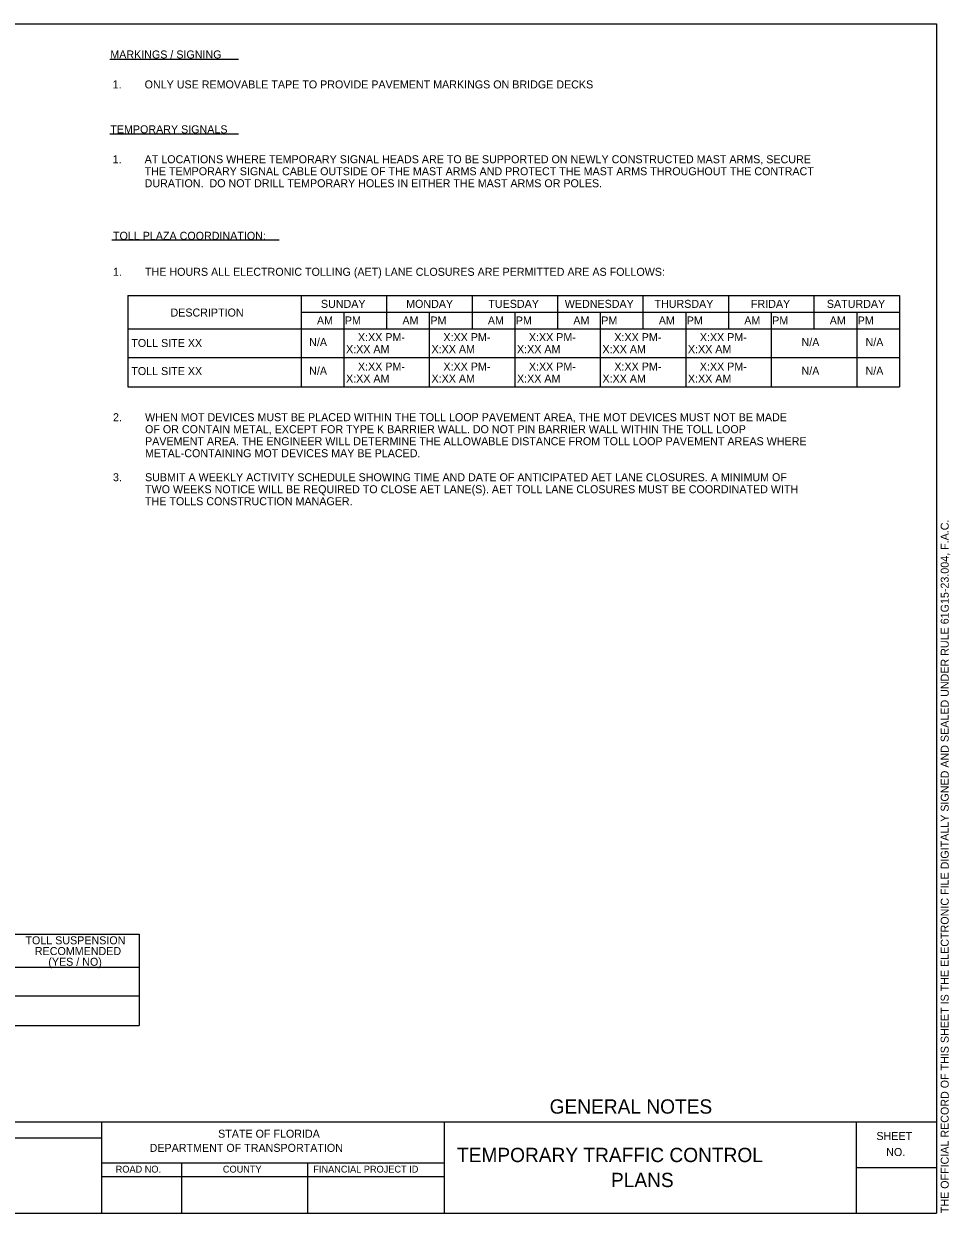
# Model space of a CAD drawing. Extents: x -0.71 to 1.34, y 0 to 0.87.
# Drawn here: x 0.664 to 1.339, y 0.004 to 0.871 of the extents above; entities that cross this region are included whole.
import ezdxf

# ---------------------------------------------------------------- set-up
doc = ezdxf.new("R2010")
doc.units = 0
for name, color, linetype in [('Default', 7, 'Continuous'), ('SheetBorder_dp', 7, 'Continuous'), ('SheetLines_dp', 7, 'Continuous'), ('TextLabel', 7, 'Continuous'), ('TextMisc', 7, 'Continuous')]:
    doc.layers.add(name, color=color, linetype=linetype)

msp = doc.modelspace()

# ---------------------------------------------------------------- linework, layer by layer
at = {"layer": 'Default'}
for p, q in [((0.74007, 0.67283), (1.30218, 0.67283)), ((0.74007, 0.67283), (0.74007, 0.60627)), ((0.86628, 0.67283), (0.86628, 0.60627)), ((0.92855, 0.67283), (0.92855, 0.64857)), ((0.99082, 0.67283), (0.99082, 0.64857)), ((1.05309, 0.67283), (1.05309, 0.64857)), ((1.11536, 0.67283), (1.11536, 0.64857)), ((1.17763, 0.67283), (1.17763, 0.64857)), ((1.2399, 0.67283), (1.2399, 0.64857)), ((1.30218, 0.67283), (1.30218, 0.60627)), ((0.86628, 0.6607), (1.30218, 0.6607)), ((0.89741, 0.6607), (0.89741, 0.60627)), ((0.95968, 0.6607), (0.95968, 0.60627)), ((1.02196, 0.6607), (1.02196, 0.60627)), ((1.08423, 0.6607), (1.08423, 0.60627)), ((1.1465, 0.6607), (1.1465, 0.60627)), ((1.20877, 0.6607), (1.20877, 0.60627)), ((1.27104, 0.6607), (1.27104, 0.60627)), ((0.74007, 0.64857), (1.30218, 0.64857)), ((0.74007, 0.62768), (1.30218, 0.62768)), ((0.74007, 0.60627), (1.30218, 0.60627)), ((0.08359, 0.20761), (0.74834, 0.20761)), ((0.74834, 0.20761), (0.74834, 0.14105)), ((0.08359, 0.18334), (0.74834, 0.18334)), ((0.08359, 0.16246), (0.74834, 0.16246)), ((0.08359, 0.14105), (0.74834, 0.14105))]:
    msp.add_line(p, q, dxfattribs=at)
at = {"layer": 'SheetBorder_dp'}
for p, q in [((0.04583, 0.87083), (1.32916, 0.87083)), ((1.32916, 0.87083), (1.32916, 0.00417)), ((0.04583, 0.07083), (1.32916, 0.07083)), ((0.04583, 0.00417), (1.32916, 0.00417))]:
    msp.add_line(p, q, dxfattribs=at)
at = {"layer": 'SheetLines_dp'}
for p, q in [((0.72083, 0.07083), (0.72083, 0.00417)), ((0.97083, 0.00417), (0.97083, 0.07083)), ((1.27083, 0.00417), (1.27083, 0.07083)), ((0.52621, 0.05917), (0.72084, 0.05917)), ((0.72083, 0.04083), (0.97083, 0.04083)), ((0.77916, 0.04083), (0.77916, 0.00417)), ((0.87083, 0.04083), (0.87083, 0.00417)), ((1.27083, 0.0375), (1.32916, 0.0375)), ((0.72083, 0.03083), (0.97083, 0.03083))]:
    msp.add_line(p, q, dxfattribs=at)
at = {"layer": 'TextLabel'}
for p, q in [((0.72696, 0.84513), (0.8207, 0.84513)), ((0.72696, 0.79059), (0.8207, 0.79059)), ((0.7283, 0.71335), (0.85036, 0.71335))]:
    msp.add_line(p, q, dxfattribs=at)

# ---------------------------------------------------------------- texts
at = {"layer": 'Default'}
for s, height, p in [('SUNDAY', 0.005833, (0.88069, 0.66385)), ('MONDAY', 0.005833, (0.94278, 0.66385)), ('TUESDAY', 0.005833, (1.0027, 0.66385)), ('WEDNESDAY', 0.005833, (1.05836, 0.66385)), ('THURSDAY', 0.005833, (1.12372, 0.66385)), ('FRIDAY', 0.005833, (1.19401, 0.66385)), ('SATURDAY', 0.005833, (1.24932, 0.66385)), ('DESCRIPTION', 0.0058333, (0.77108, 0.65751)), ('AM    PM', 0.005833, (0.87779, 0.65172)), ('AM    PM', 0.005833, (0.94006, 0.65172)), ('AM    PM', 0.005833, (1.00233, 0.65172)), ('AM    PM', 0.005833, (1.0646, 0.65172)), ('AM    PM', 0.005833, (1.12687, 0.65172)), ('AM    PM', 0.005833, (1.18914, 0.65172)), ('AM    PM', 0.005833, (1.25141, 0.65172)), ('N/A', 0.005833, (0.87214, 0.63594)), (' X:XX PM-', 0.005833, (0.9055, 0.63958)), (' X:XX PM-', 0.005833, (0.96777, 0.63958)), (' X:XX PM-', 0.005833, (1.03005, 0.63958)), (' X:XX PM-', 0.005833, (1.09232, 0.63958)), (' X:XX PM-', 0.005833, (1.15459, 0.63958)), ('N/A', 0.005833, (1.23085, 0.63594)), ('N/A', 0.005833, (1.27751, 0.63594)), ('TOLL SITE XX', 0.0058333, (0.74255, 0.63532)), ('      X:XX AM', 0.0058333, (0.886, 0.63083)), ('      X:XX AM', 0.0058333, (0.94828, 0.63083)), ('      X:XX AM', 0.0058333, (1.01055, 0.63083)), ('      X:XX AM', 0.0058333, (1.07282, 0.63083)), ('      X:XX AM', 0.0058333, (1.13509, 0.63083)), (' X:XX PM-', 0.005833, (0.9055, 0.61817)), (' X:XX PM-', 0.005833, (0.96777, 0.61817)), (' X:XX PM-', 0.005833, (1.03005, 0.61817)), (' X:XX PM-', 0.005833, (1.09232, 0.61817)), (' X:XX PM-', 0.005833, (1.15459, 0.61817)), ('TOLL SITE XX', 0.0058333, (0.74255, 0.61487)), ('N/A', 0.005833, (0.87214, 0.61506)), ('N/A', 0.005833, (1.23085, 0.61506)), ('N/A', 0.005833, (1.27751, 0.61506)), ('      X:XX AM', 0.0058333, (0.886, 0.60942)), ('      X:XX AM', 0.0058333, (0.94828, 0.60942)), ('      X:XX AM', 0.0058333, (1.01055, 0.60942)), ('      X:XX AM', 0.0058333, (1.07282, 0.60942)), ('      X:XX AM', 0.0058333, (1.13509, 0.60942)), ('TOLL SUSPENSION ', 0.0058333, (0.66541, 0.20009)), ('RECOMMENDED', 0.0058333, (0.67228, 0.19227)), ('(YES / NO)', 0.005833, (0.68208, 0.18446))]:
    msp.add_text(s, height=height, dxfattribs=at).set_placement(p)
at = {"layer": 'TextLabel'}
for s, height, p in [('MARKINGS / SIGNING', 0.0058333, (0.72723, 0.84555)), ('1. ', 0.005833, (0.72892, 0.82374)), ('ONLY USE REMOVABLE TAPE TO PROVIDE PAVEMENT MARKINGS ON BRIDGE DECKS', 0.0058333, (0.75225, 0.82374)), ('TEMPORARY SIGNALS', 0.0058333, (0.72723, 0.79102)), ('1. ', 0.005833, (0.72892, 0.76921)), ('AT LOCATIONS WHERE TEMPORARY SIGNAL HEADS ARE TO BE SUPPORTED ON NEWLY CONSTRUCTED MAST ARMS, SECURE ', 0.00583333, (0.75225, 0.76921)), ('THE TEMPORARY SIGNAL CABLE OUTSIDE OF THE MAST ARMS AND PROTECT THE MAST ARMS THROUGHOUT THE CONTRACT ', 0.00583333, (0.75225, 0.76046)), ('DURATION.  DO NOT DRILL TEMPORARY HOLES IN EITHER THE MAST ARMS OR POLES.', 0.0058333, (0.75225, 0.75171)), ('TOLL PLAZA COORDINATION:', 0.0058333, (0.7292, 0.71344)), ('THE HOURS ALL ELECTRONIC TOLLING (AET) LANE CLOSURES ARE PERMITTED ARE AS FOLLOWS:', 0.0058333, (0.75254, 0.68719)), ('1.', 0.005833, (0.7292, 0.68719)), ('2. ', 0.005833, (0.7292, 0.58126)), ('WHEN MOT DEVICES MUST BE PLACED WITHIN THE TOLL LOOP PAVEMENT AREA, THE MOT DEVICES MUST NOT BE MADE  ', 0.00583333, (0.75254, 0.58126)), ('OF OR CONTAIN METAL, EXCEPT FOR TYPE K BARRIER WALL. DO NOT PIN BARRIER WALL WITHIN THE TOLL LOOP ', 0.0058333, (0.75254, 0.57251)), ('PAVEMENT AREA. THE ENGINEER WILL DETERMINE THE ALLOWABLE DISTANCE FROM TOLL LOOP PAVEMENT AREAS WHERE ', 0.00583333, (0.75254, 0.56376)), ('METAL-CONTAINING MOT DEVICES MAY BE PLACED.', 0.0058333, (0.75254, 0.55501)), ('3. ', 0.005833, (0.7292, 0.53751)), ('SUBMIT A WEEKLY ACTIVITY SCHEDULE SHOWING TIME AND DATE OF ANTICIPATED AET LANE CLOSURES. A MINIMUM OF ', 0.00583333, (0.75254, 0.53751)), ('TWO WEEKS NOTICE WILL BE REQUIRED TO CLOSE AET LANE(S). AET TOLL LANE CLOSURES MUST BE COORDINATED WITH ', 0.00583333, (0.75254, 0.52876)), ('THE TOLLS CONSTRUCTION MANAGER.', 0.0058333, (0.75254, 0.52001))]:
    msp.add_text(s, height=height, dxfattribs=at).set_placement(p)
at = {"layer": 'TextMisc'}
for s, height, rotation, p in [('THE OFFICIAL RECORD OF THIS SHEET IS THE ELECTRONIC FILE DIGITALLY SIGNED AND SEALED UNDER RULE 61G15-23.004, F.A.C.', 0.00583333, 90, (1.33811, 0.00419)), ('SHEET', 0.005833, 359.86066, (1.2854, 0.05754)), ('NO.', 0.005833, 359.86066, (1.29254, 0.04586))]:
    msp.add_text(s, height=height, rotation=rotation, dxfattribs=at).set_placement(p)
for s, height, p in [('GENERAL NOTES', 0.0104166, (1.04734, 0.07671)), ('STATE OF FLORIDA', 0.0058333, (0.80578, 0.05918)), ('DEPARTMENT OF TRANSPORTATION', 0.0058333, (0.75589, 0.04888)), ('TEMPORARY TRAFFIC CONTROL ', 0.0104166, (0.97984, 0.04141)), ('ROAD NO.', 0.005, (0.73115, 0.03376)), ('COUNTY', 0.005, (0.80925, 0.03376)), ('FINANCIAL PROJECT ID', 0.005, (0.87518, 0.03376)), ('PLANS', 0.010417, (1.09204, 0.02318))]:
    msp.add_text(s, height=height, dxfattribs=at).set_placement(p)

doc.saveas('drawing.dxf')
